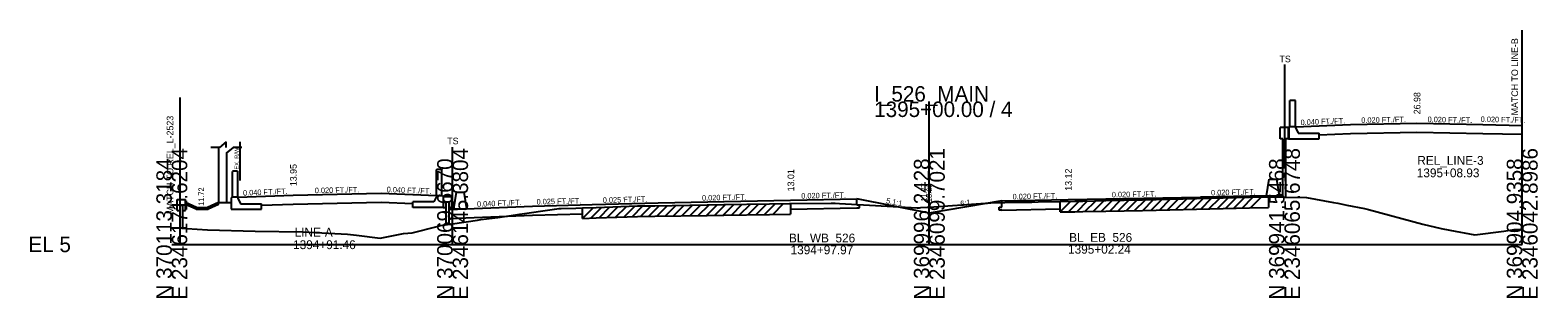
# Model space of a CAD drawing. Extents: x -170 to 2527928, y -10 to 1619750.
# Drawn here: x 1974.3 to 2247.8, y 6490.3 to 6538.9 of the extents above; entities that cross this region are included whole.
import ezdxf

# ---------------------------------------------------------------- set-up
doc = ezdxf.new("R2010")
doc.units = 0
for name, color, linetype in [('Default', 7, 'Continuous'), ('RD_GPK_XS_Cell', 7, 'Continuous'), ('RD_PD_NOISE-WALL-GM', 7, 'Continuous'), ('RD_PD_WallFill', 7, 'Continuous'), ('RD_XS_Base', 7, 'Continuous'), ('RD_XS_EarthShd', 7, 'Continuous'), ('RD_XS_ExGround', 7, 'Continuous'), ('RD_XS_ExPaveRet', 7, 'Continuous'), ('RD_XS_ExRW', 7, 'Continuous'), ('RD_XS_MatchLine', 7, 'Continuous'), ('RD_XS_Pave', 7, 'Continuous'), ('RD_XS_PaveShd', 7, 'Continuous'), ('RD_XS_TieSlope', 7, 'Continuous'), ('RD_XS_TX_Elev_EX', 7, 'Continuous'), ('RD_XS_TX_Elev_PR', 7, 'Continuous'), ('RD_XS_TX_Slope', 7, 'Continuous'), ('RD_XS_TX_Station', 7, 'Continuous')]:
    doc.layers.add(name, color=color, linetype=linetype)

msp = doc.modelspace()

# ---------------------------------------------------------------- linework, layer by layer
at = {"layer": 'Default'}
for p, q in [((2008.63, 6517.58), (2007.05, 6517.58)), ((2009.88, 6518.61), (2008.63, 6517.58)), ((2009.88, 6517.58), (2009.88, 6518.61)), ((2011.13, 6517.58), (2009.88, 6516.56)), ((2012.72, 6517.58), (2011.13, 6517.58))]:
    msp.add_line(p, q, dxfattribs=at)
at = {"layer": 'RD_GPK_XS_Cell'}
for p, q in [((2137.4, 6500), (2137.4, 6525.91)), ((2000, 6500), (2050.93, 6500)), ((2050.93, 6500), (2137.4, 6500)), ((2137.4, 6500), (2201.82, 6500)), ((2201.82, 6500), (2244.94, 6500))]:
    msp.add_line(p, q, dxfattribs=at)
at = {"layer": 'RD_PD_NOISE-WALL-GM'}
for p, q in [((2008.5, 6517.58), (2008.5, 6507.63)), ((2010, 6507.63), (2010, 6516.66)), ((2198.57, 6508.84), (2199.05, 6511.84)), ((2199.05, 6511.84), (2200.39, 6511.84)), ((2200.39, 6511.84), (2200.87, 6508.84)), ((2051.13, 6506.48), (2051.61, 6509.48)), ((2051.61, 6509.48), (2052.95, 6509.48)), ((2052.95, 6509.48), (2053.43, 6506.48)), ((2051.13, 6506.48), (2053.43, 6506.48))]:
    msp.add_line(p, q, dxfattribs=at)
at = {"layer": 'RD_PD_WallFill'}
for p, q in [((2202.82, 6521.34), (2202.82, 6526.1)), ((2203.82, 6526.1), (2202.82, 6526.1)), ((2203.82, 6521.34), (2203.82, 6526.1)), ((2201.04, 6519.18), (2201.04, 6521.18)), ((2202.54, 6521.18), (2201.04, 6521.18)), ((2202.69, 6521.34), (2202.53, 6521.18)), ((2202.54, 6519.18), (2202.54, 6521.18)), ((2202.61, 6521.18), (2202.54, 6521.18)), ((2202.61, 6521.26), (2202.61, 6519.18)), ((2203.82, 6521.34), (2202.69, 6521.34)), ((2203.82, 6521.34), (2203.82, 6521.18)), ((2203.82, 6521.18), (2204.31, 6520.18)), ((2204.31, 6520.18), (2208.11, 6520.18)), ((2208.11, 6519.18), (2208.11, 6520.18)), ((2244.94, 6502.75), (2244.94, 6521.6)), ((2201.54, 6519.18), (2201.04, 6519.18)), ((2201.54, 6508.59), (2201.54, 6519.18)), ((2202.04, 6508.58), (2202.04, 6519.18)), ((2202.54, 6519.18), (2202.04, 6519.18)), ((2202.54, 6519.18), (2208.11, 6519.18)), ((2202.61, 6519.18), (2202.54, 6519.18)), ((2011.08, 6513.31), (2011, 6513.22)), ((2011, 6508.55), (2011, 6513.22)), ((2011.92, 6513.31), (2011.08, 6513.31)), ((2011.92, 6513.31), (2012, 6513.22)), ((2012, 6508.55), (2012, 6513.22)), ((2048.08, 6513.63), (2048, 6513.54)), ((2048, 6508.87), (2048, 6513.54)), ((2048.08, 6513.63), (2048.92, 6513.63)), ((2048.92, 6513.63), (2049, 6513.54)), ((2049, 6508.87), (2049, 6513.54)), ((2048, 6508.71), (2047.51, 6507.71)), ((2048, 6508.87), (2049.13, 6508.87)), ((2048, 6508.87), (2048, 6508.71)), ((2049.13, 6508.87), (2049.29, 6508.71)), ((2049.21, 6508.79), (2049.21, 6506.71)), ((2049.21, 6508.71), (2049.28, 6508.71)), ((2049.28, 6506.71), (2049.28, 6508.71)), ((2049.28, 6508.71), (2050.78, 6508.71)), ((2050.78, 6506.71), (2050.78, 6508.71)), ((2198.57, 6508.84), (2201.54, 6508.84)), ((2001, 6508.13), (2002.5, 6508.13)), ((2001, 6506.13), (2001, 6508.13)), ((2001, 6506.13), (2001.5, 6506.13)), ((2001.5, 6502.96), (2001.5, 6507.13)), ((2001.5, 6507.13), (2002, 6507.13)), ((2002, 6502.93), (2002, 6507.13)), ((2002, 6506.13), (2002.5, 6506.13)), ((2002.5, 6506.13), (2002.5, 6508.13)), ((2004.5, 6506.72), (2002.5, 6507.63)), ((2004.43, 6506.38), (2002.5, 6507.27)), ((2004.43, 6506.38), (2006.57, 6506.38)), ((2004.5, 6506.72), (2006.5, 6506.72)), ((2008.5, 6507.63), (2006.5, 6506.72)), ((2008.5, 6507.27), (2006.57, 6506.38)), ((2008.5, 6507.27), (2008.5, 6507.63)), ((2010.87, 6508.55), (2010.79, 6508.47)), ((2010.79, 6508.47), (2010.79, 6506.39)), ((2010.79, 6506.39), (2016.29, 6506.39)), ((2012, 6508.55), (2010.87, 6508.55)), ((2012, 6508.55), (2012, 6508.39)), ((2012, 6508.39), (2012.49, 6507.39)), ((2012.49, 6507.39), (2016.29, 6507.39)), ((2016.29, 6506.39), (2016.29, 6507.39)), ((2047.51, 6507.71), (2043.71, 6507.71)), ((2043.71, 6506.71), (2043.71, 6507.71)), ((2049.28, 6506.71), (2043.71, 6506.71)), ((2049.21, 6506.71), (2049.28, 6506.71)), ((2049.28, 6506.71), (2049.78, 6506.71)), ((2049.78, 6507.71), (2050.28, 6507.71)), ((2049.78, 6503.59), (2049.78, 6507.71)), ((2050.28, 6503.67), (2050.28, 6507.71)), ((2050.28, 6506.71), (2050.78, 6506.71))]:
    msp.add_line(p, q, dxfattribs=at)
at = {"layer": 'RD_XS_Base'}
for p, q in [((2208.11, 6519.88), (2213.82, 6520.11)), ((2213.82, 6520.11), (2225.82, 6520.35)), ((2225.82, 6520.35), (2237.82, 6520.11)), ((2237.82, 6520.11), (2244.94, 6519.97)), ((2198.57, 6508.63), (2198.57, 6508.84)), ((2016.29, 6507.09), (2022, 6507.32)), ((2022, 6507.32), (2038, 6507.64)), ((2038, 6507.64), (2043.71, 6507.41)), ((2050.28, 6504.72), (2050.28, 6506.35)), ((2112.22, 6506.37), (2124.24, 6506.61)), ((2124.24, 6507.11), (2124.24, 6508.25)), ((2124.74, 6507.12), (2124.24, 6507.11)), ((2124.24, 6506.61), (2124.74, 6506.62)), ((2124.74, 6506.62), (2124.74, 6507.12)), ((2150.07, 6506.73), (2150.57, 6506.74)), ((2150.07, 6506.23), (2150.07, 6506.73)), ((2150.57, 6506.24), (2150.07, 6506.23)), ((2150.57, 6506.74), (2150.57, 6507.88)), ((2150.57, 6506.24), (2161.13, 6506.45)), ((2050.28, 6504.72), (2065.43, 6505.32)), ((2065.43, 6505.32), (2074.49, 6505.55))]:
    msp.add_line(p, q, dxfattribs=at)
at = {"layer": 'RD_XS_EarthShd'}
msp.add_line((2008.5, 6507.63), (2010.79, 6507.63), dxfattribs=at)
at = {"layer": 'RD_XS_ExGround'}
msp.add_lwpolyline([(2000, 6503.03), (2000.84, 6503), (2006.45, 6502.67), (2015.1, 6502.38), (2023.75, 6502.28), (2031.85, 6501.87), (2033.48, 6501.68), (2037.81, 6501.13), (2042.05, 6501.96), (2043.6, 6502.09), (2048.15, 6503.27), (2048.66, 6503.43), (2050.93, 6503.76), (2055.45, 6504.41), (2056.05, 6504.5), (2059.16, 6504.88), (2063.11, 6505.51), (2069.41, 6506.39), (2070.27, 6506.5), (2070.61, 6506.52), (2073.26, 6506.6), (2074.49, 6506.63), (2076.95, 6506.71), (2084.45, 6506.97), (2087.6, 6507.02), (2097.1, 6507.18), (2100.14, 6507.23), (2108.42, 6507.36), (2112.05, 6507.43), (2112.22, 6507.43), (2119.6, 6507.5), (2120.04, 6507.5), (2120.31, 6507.47), (2121.1, 6507.42), (2135.19, 6506.66), (2135.27, 6506.66), (2135.4, 6506.66), (2135.64, 6506.66), (2135.85, 6506.67), (2137.4, 6506.77), (2147.62, 6507.47), (2147.93, 6507.5), (2148.58, 6507.52), (2153.63, 6507.64), (2156, 6507.69), (2157.13, 6507.73), (2161.13, 6507.81), (2163.79, 6507.84), (2165.23, 6507.87), (2169.43, 6507.95), (2176.07, 6508.09), (2181.05, 6508.2), (2188.3, 6508.37), (2195.45, 6508.55), (2198.9, 6508.64), (2200.51, 6508.61), (2201.82, 6508.58), (2205.83, 6508.5), (2210.74, 6507.63), (2211.47, 6507.51), (2213.13, 6507.15), (2216.33, 6506.5), (2217.09, 6506.34), (2226.91, 6503.69), (2230.26, 6502.88), (2231.79, 6502.56), (2236.35, 6501.74), (2241.63, 6502.42), (2243.49, 6502.69), (2244.94, 6502.75)], dxfattribs=at)
at = {"layer": 'RD_XS_ExPaveRet'}
for p, q in [((2198.9, 6508.64), (2198.9, 6506.72)), ((2074.49, 6504.71), (2076.48, 6506.7)), ((2074.49, 6504.71), (2074.49, 6506.63)), ((2075.99, 6504.76), (2077.98, 6506.75)), ((2077.49, 6504.81), (2079.48, 6506.8)), ((2078.99, 6504.87), (2080.98, 6506.85)), ((2080.49, 6504.92), (2082.48, 6506.9)), ((2081.99, 6504.97), (2083.98, 6506.95)), ((2083.49, 6505.02), (2085.46, 6506.98)), ((2084.99, 6505.06), (2086.94, 6507.01)), ((2086.49, 6505.08), (2088.44, 6507.03)), ((2087.99, 6505.11), (2089.94, 6507.06)), ((2089.49, 6505.13), (2091.44, 6507.08)), ((2090.99, 6505.16), (2092.94, 6507.11)), ((2092.49, 6505.18), (2094.44, 6507.13)), ((2093.99, 6505.21), (2095.94, 6507.16)), ((2095.49, 6505.23), (2097.44, 6507.18)), ((2096.99, 6505.26), (2098.94, 6507.21)), ((2098.49, 6505.28), (2100.44, 6507.23)), ((2099.99, 6505.31), (2101.94, 6507.25)), ((2101.49, 6505.33), (2103.44, 6507.28)), ((2102.99, 6505.35), (2104.94, 6507.3)), ((2104.49, 6505.38), (2106.44, 6507.33)), ((2105.99, 6505.4), (2107.94, 6507.35)), ((2107.49, 6505.43), (2109.44, 6507.38)), ((2108.99, 6505.45), (2110.95, 6507.41)), ((2112.22, 6507.43), (2112.22, 6505.51)), ((2161.13, 6505.9), (2163.07, 6507.84)), ((2161.13, 6505.9), (2161.13, 6507.81)), ((2161.13, 6505.9), (2163.79, 6505.93)), ((2162.63, 6505.91), (2164.58, 6507.86)), ((2163.79, 6505.93), (2165.23, 6505.95)), ((2164.13, 6505.93), (2166.08, 6507.88)), ((2165.23, 6505.95), (2169.43, 6506.04)), ((2165.63, 6505.96), (2167.59, 6507.91)), ((2167.13, 6505.99), (2169.09, 6507.95)), ((2168.63, 6506.02), (2170.59, 6507.98)), ((2169.43, 6506.04), (2176.07, 6506.17)), ((2170.13, 6506.05), (2172.09, 6508.01)), ((2171.63, 6506.08), (2173.59, 6508.04)), ((2173.13, 6506.11), (2175.09, 6508.07)), ((2174.63, 6506.14), (2176.59, 6508.1)), ((2176.07, 6506.17), (2181.05, 6506.29)), ((2176.13, 6506.18), (2178.09, 6508.14)), ((2177.63, 6506.21), (2179.59, 6508.17)), ((2179.13, 6506.24), (2181.09, 6508.2)), ((2180.63, 6506.28), (2182.6, 6508.24)), ((2181.05, 6506.29), (2188.3, 6506.45)), ((2182.13, 6506.31), (2184.1, 6508.27)), ((2183.63, 6506.34), (2185.6, 6508.31)), ((2185.13, 6506.38), (2187.1, 6508.34)), ((2186.63, 6506.41), (2188.6, 6508.38)), ((2188.13, 6506.45), (2190.1, 6508.41)), ((2188.3, 6506.45), (2195.45, 6506.63)), ((2189.63, 6506.48), (2191.6, 6508.45)), ((2191.13, 6506.52), (2193.1, 6508.49)), ((2192.63, 6506.56), (2194.6, 6508.53)), ((2194.13, 6506.6), (2196.1, 6508.57)), ((2195.45, 6506.63), (2198.9, 6506.72)), ((2195.63, 6506.64), (2197.6, 6508.6)), ((2074.49, 6504.71), (2076.95, 6504.8)), ((2076.95, 6504.8), (2084.45, 6505.05)), ((2084.45, 6505.05), (2087.6, 6505.1)), ((2087.6, 6505.1), (2097.1, 6505.26)), ((2097.1, 6505.26), (2100.14, 6505.31)), ((2100.14, 6505.31), (2108.42, 6505.44)), ((2108.42, 6505.44), (2112.05, 6505.51)), ((2112.05, 6505.51), (2112.22, 6505.51))]:
    msp.add_line(p, q, dxfattribs=at)
at = {"layer": 'RD_XS_ExRW'}
msp.add_line((2012.4, 6511.62), (2012.4, 6518.62), dxfattribs=at)
at = {"layer": 'RD_XS_MatchLine'}
for p, q in [((2244.94, 6500), (2244.94, 6538.87)), ((2201.82, 6532.66), (2201.82, 6513.78)), ((2001.5, 6500), (2001.5, 6526.65)), ((2050.93, 6500), (2050.93, 6517.65))]:
    msp.add_line(p, q, dxfattribs=at)
at = {"layer": 'RD_XS_Pave'}
for p, q in [((2213.82, 6521.74), (2225.82, 6521.98)), ((2225.82, 6521.98), (2237.82, 6521.74)), ((2022, 6508.95), (2038, 6509.27)), ((2065.43, 6506.96), (2076.24, 6507.23)), ((2076.24, 6507.23), (2088.24, 6507.53)), ((2088.24, 6507.53), (2112.24, 6508.01)), ((2162.57, 6508.12), (2186.57, 6508.6))]:
    msp.add_line(p, q, dxfattribs=at)
at = {"layer": 'RD_XS_PaveShd'}
for p, q in [((2203.82, 6521.34), (2213.82, 6521.74)), ((2237.82, 6521.74), (2244.94, 6521.6)), ((2012, 6508.55), (2022, 6508.95)), ((2038, 6509.27), (2048, 6508.87)), ((2198.57, 6508.84), (2186.57, 6508.6)), ((2050.28, 6506.35), (2065.43, 6506.96)), ((2112.24, 6508.01), (2124.24, 6508.25)), ((2150.57, 6507.88), (2162.57, 6508.12))]:
    msp.add_line(p, q, dxfattribs=at)
at = {"layer": 'RD_XS_TieSlope'}
for p, q in [((2137.4, 6505.68), (2124.24, 6508.25)), ((2150.57, 6507.88), (2137.4, 6505.68))]:
    msp.add_line(p, q, dxfattribs=at)

# ---------------------------------------------------------------- texts
at = {"layer": 'RD_GPK_XS_Cell'}
for s, p in [('I_526_MAIN', (2127.4, 6525.91)), ('1395+00.00 / 4', (2127.4, 6523.11)), ('EL 5', (1974, 6498.6))]:
    msp.add_text(s, height=2.8, dxfattribs=at).set_placement(p)
for s, p in [('E 2346171.6204', (2002.8, 6490)), ('E 2346145.3804', (2053.73, 6490)), ('E 2346099.7021', (2140.2, 6490)), ('E 2346065.6748', (2204.62, 6490)), ('E 2346042.8986', (2247.74, 6490)), ('N 370113.3184', (2000, 6490)), ('N 370069.6670', (2050.93, 6490)), ('N 369996.2428', (2137.4, 6490)), ('N 369941.5468', (2201.82, 6490)), ('N 369904.9358', (2244.94, 6490))]:
    msp.add_text(s, height=2.8, rotation=90, dxfattribs=at).set_placement(p)
at = {"layer": 'RD_XS_ExRW'}
msp.add_text('EX. R/W ', height=0.75, rotation=90, dxfattribs=at).set_placement((2012.15, 6513.57))
at = {"layer": 'RD_XS_MatchLine'}
for s, p in [('MATCH TO LINE-B', (2244.19, 6523.41)), ('MATCH TO REL_L-2523', (2000.28, 6505.5))]:
    msp.add_text(s, height=1.2, rotation=90, dxfattribs=at).set_placement(p)
for p in [(2200.91, 6533.04), (2049.96, 6518.17)]:
    msp.add_text('TS', height=1.2, dxfattribs=at).set_placement(p)
at = {"layer": 'RD_XS_TX_Elev_EX'}
msp.add_text('11.77', height=1, rotation=90, dxfattribs=at).set_placement((2136.9, 6507.77))
at = {"layer": 'RD_XS_TX_Elev_PR'}
msp.add_text('10.68', height=1, rotation=90, dxfattribs=at).set_placement((2137.9, 6507.68))
at = {"layer": 'RD_XS_TX_Slope'}
for s, rotation, p in [('0.040 FT./FT.', 2.2906, (2204.76, 6521.63)), ('0.020 FT./FT.', 1.1458, (2215.76, 6522.03)), ('0.020 FT./FT.', 358.8542, (2227.77, 6522.19)), ('0.020 FT./FT.', 358.8542, (2237.4, 6522.22)), ('11.72', 90, (2005.84, 6507)), ('0.040 FT./FT.', 2.2906, (2012.94, 6508.84)), ('0.020 FT./FT.', 1.1458, (2025.94, 6509.28)), ('0.040 FT./FT.', 357.7094, (2038.96, 6509.48)), ('0.025 FT./FT.', 1.4321, (2078.18, 6507.53)), ('0.020 FT./FT.', 1.1458, (2096.18, 6507.94)), ('0.020 FT./FT.', 1.1458, (2114.18, 6508.3)), ('0.020 FT./FT.', 1.1458, (2152.51, 6508.16)), ('0.020 FT./FT.', 1.1458, (2170.51, 6508.52)), ('0.020 FT./FT.', 1.1458, (2188.51, 6508.88)), ('0.040 FT./FT.', 2.2906, (2055.38, 6506.81)), ('0.025 FT./FT.', 1.4321, (2066.18, 6507.23)), ('5.1:1', 348.9687, (2129.49, 6507.48)), ('6:1', 9.4623, (2143.12, 6506.89))]:
    msp.add_text(s, height=1, rotation=rotation, dxfattribs=at).set_placement(p)
at = {"layer": 'RD_XS_TX_Station'}
for s, p in [(' 26.98', (2226.48, 6523.16)), (' 13.95', (2022.66, 6510.12)), (' 13.01', (2112.89, 6509.18)), (' 13.12', (2163.23, 6509.29))]:
    msp.add_text(s, height=1.2, rotation=90, dxfattribs=at).set_placement(p)
for s, p in [('REL_LINE-3', (2225.92, 6514.44)), ('1395+08.93', (2225.82, 6512.18)), ('1394+91.46', (2022, 6499.15)), ('LINE-A', (2022.29, 6501.41)), ('BL_WB_526', (2111.94, 6500.36)), ('BL_EB_526', (2162.77, 6500.47)), ('1394+97.97', (2112.24, 6498.21)), ('1395+02.24', (2162.57, 6498.32))]:
    msp.add_text(s, height=1.6, dxfattribs=at).set_placement(p)

doc.saveas('drawing.dxf')
